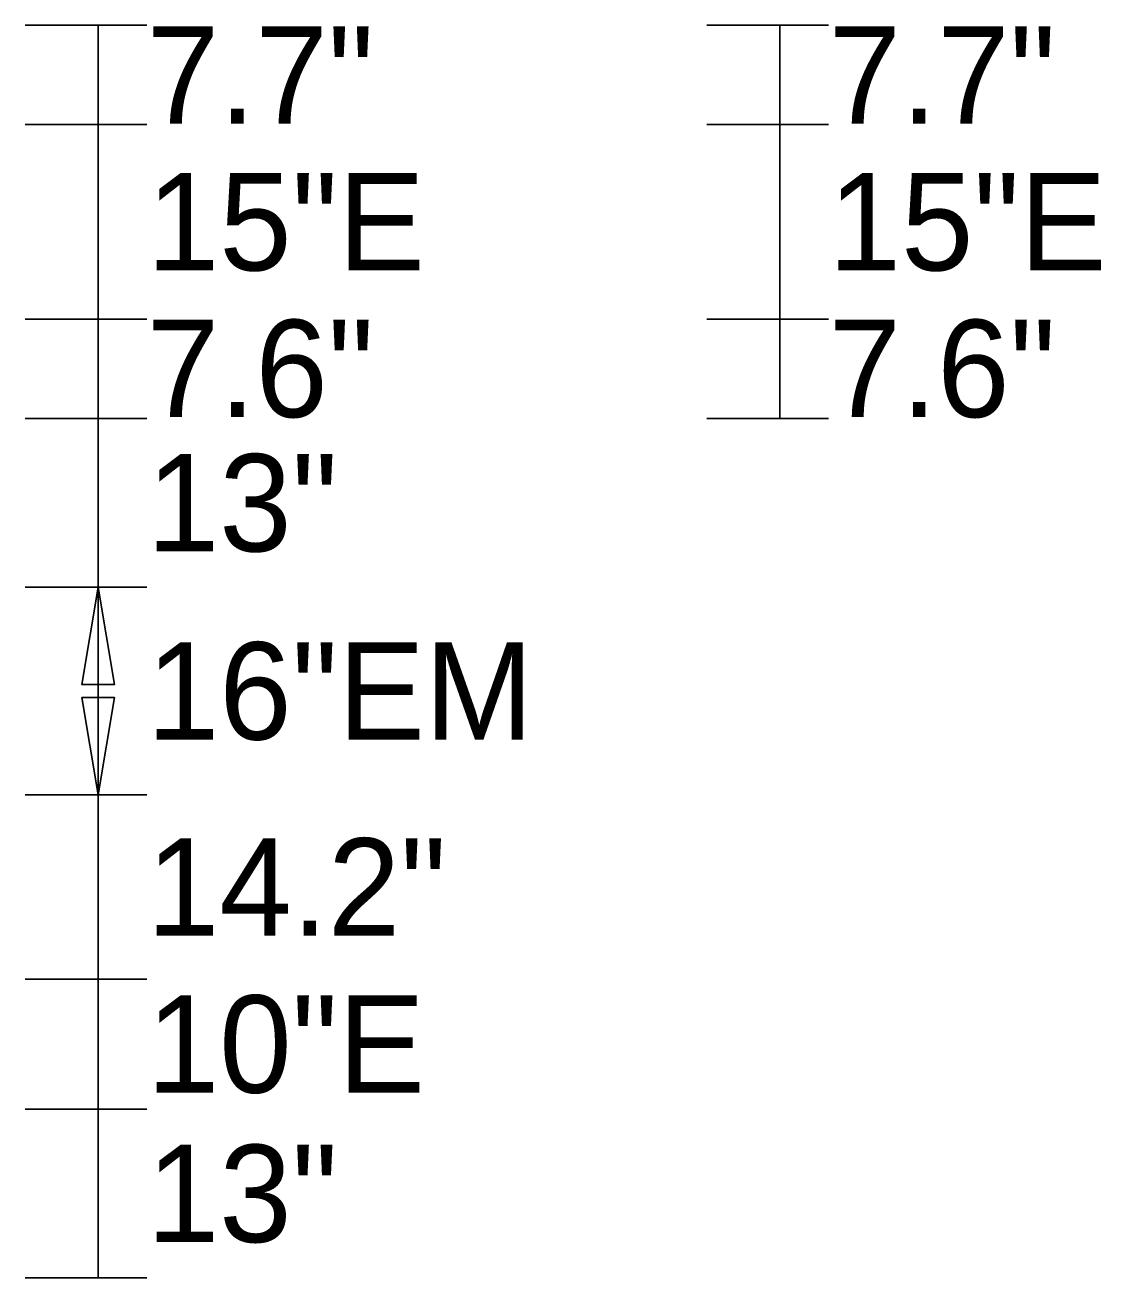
# Model space of a CAD drawing. Extents: x 1806251 to 1809821, y 414895 to 422886.
# Drawn here: x 1809678.462 to 1809679.291, y 415082.05 to 415083.015 of the extents above; entities that cross this region are included whole.
import ezdxf

# ---------------------------------------------------------------- set-up
doc = ezdxf.new("R2010")
doc.units = 0
doc.layers.add('GSDIMS', color=7, linetype='Continuous')

msp = doc.modelspace()

# ---------------------------------------------------------------- linework, layer by layer
at = {"layer": 'GSDIMS'}
for p, q in [((1809678.46225, 415083.015), (1809678.556, 415083.015)), ((1809678.5185, 415082.9385), (1809678.5185, 415083.015)), ((1809678.98725, 415083.015), (1809679.081, 415083.015)), ((1809679.0435, 415082.9385), (1809679.0435, 415083.015)), ((1809678.46225, 415082.9385), (1809678.556, 415082.9385)), ((1809678.46225, 415082.9385), (1809678.556, 415082.9385)), ((1809678.5185, 415082.9385), (1809678.5185, 415082.7885)), ((1809678.98725, 415082.9385), (1809679.081, 415082.9385)), ((1809678.98725, 415082.9385), (1809679.081, 415082.9385)), ((1809679.0435, 415082.9385), (1809679.0435, 415082.7885)), ((1809678.46225, 415082.7885), (1809678.556, 415082.7885)), ((1809678.46225, 415082.7885), (1809678.556, 415082.7885)), ((1809678.5185, 415082.712), (1809678.5185, 415082.7885)), ((1809678.98725, 415082.7885), (1809679.081, 415082.7885)), ((1809678.98725, 415082.7885), (1809679.081, 415082.7885)), ((1809679.0435, 415082.712), (1809679.0435, 415082.7885)), ((1809678.46225, 415082.712), (1809678.556, 415082.712)), ((1809678.46225, 415082.712), (1809678.556, 415082.712)), ((1809678.5185, 415082.58207), (1809678.5185, 415082.712)), ((1809678.98725, 415082.712), (1809679.081, 415082.712)), ((1809678.46225, 415082.58207), (1809678.556, 415082.58207)), ((1809678.46225, 415082.58207), (1809678.556, 415082.58207)), ((1809678.5185, 415082.58207), (1809678.5185, 415082.42207)), ((1809678.46225, 415082.42207), (1809678.556, 415082.42207)), ((1809678.46225, 415082.42207), (1809678.556, 415082.42207)), ((1809678.5185, 415082.28007), (1809678.5185, 415082.42207)), ((1809678.46225, 415082.28007), (1809678.556, 415082.28007)), ((1809678.46225, 415082.28007), (1809678.556, 415082.28007)), ((1809678.5185, 415082.28007), (1809678.5185, 415082.18007)), ((1809678.46225, 415082.18007), (1809678.556, 415082.18007)), ((1809678.46225, 415082.18007), (1809678.556, 415082.18007)), ((1809678.5185, 415082.05), (1809678.5185, 415082.18007)), ((1809678.46225, 415082.05), (1809678.556, 415082.05))]:
    msp.add_line(p, q, dxfattribs=at)
for points in [[(1809678.5185, 415082.58207), (1809678.506, 415082.50707), (1809678.531, 415082.50707)], [(1809678.5185, 415082.42207), (1809678.506, 415082.49707), (1809678.531, 415082.49707)]]:
    msp.add_lwpolyline(points, close=True, dxfattribs=at)

# ---------------------------------------------------------------- texts
for s, p in [('7.7"', (1809678.556, 415082.939)), ('7.7"', (1809679.081, 415082.939)), ('15"E', (1809678.556, 415082.826)), ('15"E', (1809679.081, 415082.826)), ('7.6"', (1809678.556, 415082.713)), ('7.6"', (1809679.081, 415082.713)), ('13"', (1809678.556, 415082.60957)), ('16"EM', (1809678.556, 415082.46465)), ('14.2"', (1809678.556, 415082.31365)), ('10"E', (1809678.556, 415082.19265)), ('13"', (1809678.556, 415082.07757))]:
    msp.add_text(s, height=0.075, dxfattribs=at).set_placement(p)

doc.saveas('drawing.dxf')
